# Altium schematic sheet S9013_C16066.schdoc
size 127 x 101 mm
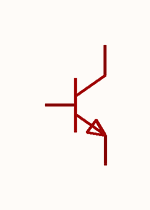
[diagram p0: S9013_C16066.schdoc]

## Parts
Q?  s9013(range:144-202)  [TO-92-3_L4.9-W3.7-P1.27-L]  (value not drawn)

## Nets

Not connected (* = marked no-connect by the designer): Q? 1(E) 2(B) 3(C)

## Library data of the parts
Q? = s9013(range:144-202): 晶体管类型:NPN;集电极电流(Ic):500mA;集射极击穿电压(Vceo):25V;耗散功率(Pd):625mW;直流电流增益(hFE):144;; Manufacturer: CJ(江苏长电/长晶); Symbol: S9013_C16066; AddInBom: yes; ModelId: aafe8e06f2154e7c93506efd0d6632dd; ModelTransform: 176.28752,144.88554,0,180,0,0,0,20.669,-196.85; type: NPN; Current - Collector(Ic): 500mA; Collector - Emitter Voltage VCEO: 25V; Pd - Power Dissipation: 625mW; DC Current Gain: 144; Transition frequency(fT): 150MHz; Current - Collector Cutoff: 100nA; Vce Saturation(VCE(sat)): 600mV; Emitter-Base Voltage(Vebo): 5V; Number: 1个NPN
